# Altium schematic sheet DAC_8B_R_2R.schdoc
size 297 x 209 mm; Symbol: Drawing-Symbol_A4; @Project Name: Inverted_MAML_6x6; @Page Count: 1; @Update Date: 2026-06-15; @Create Date: 2026-06-15; @Schematic Name: Schematic1; @Page No: 1; @Page Name: P1; Company: EasyEDA.com; Version: V1.0; Page Size: A4; Drawn: Olle Welin; Device: Drawing-Symbol_A4; @Create Time: 20:58:38; @Update Time: 20:58:38; Border: 1; Width: 1170; Height: 825; Region Start: 1; X Region Count: 6; Y Region Count: 4; Blade Width: 10; Title Block Position: 3
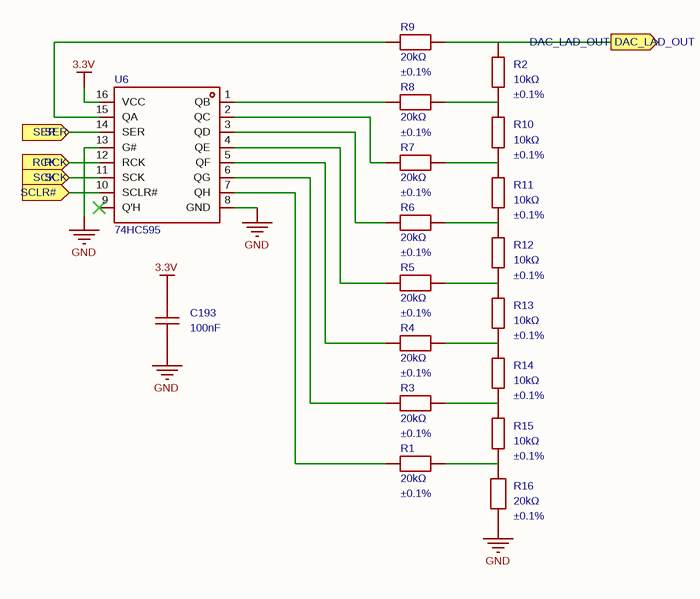
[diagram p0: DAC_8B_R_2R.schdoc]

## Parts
C193  100nF  [C0402]
R1  20kΩ  Tolerance: ±0.1%  [R0402]
R2  10kΩ  Tolerance: ±0.1%  [R0402]
R3  20kΩ  Tolerance: ±0.1%  [R0402]
R4  20kΩ  Tolerance: ±0.1%  [R0402]
R5  20kΩ  Tolerance: ±0.1%  [R0402]
R6  20kΩ  Tolerance: ±0.1%  [R0402]
R7  20kΩ  Tolerance: ±0.1%  [R0402]
R8  20kΩ  Tolerance: ±0.1%  [R0402]
R9  20kΩ  Tolerance: ±0.1%  [R0402]
R10  10kΩ  Tolerance: ±0.1%  [R0402]
R11  10kΩ  Tolerance: ±0.1%  [R0402]
R12  10kΩ  Tolerance: ±0.1%  [R0402]
R13  10kΩ  Tolerance: ±0.1%  [R0402]
R14  10kΩ  Tolerance: ±0.1%  [R0402]
R15  10kΩ  Tolerance: ±0.1%  [R0402]
R16  20kΩ  Tolerance: ±0.1%  [R0402]
U6  74HC595  [SOP-16_L9.9-W3.9-P1.27-LS6.0-BL]

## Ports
DAC_LAD_OUT (out), RCK (in), SCK (in), SCLR# (in), SER (in)

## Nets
3.3V: C193.2 U6.16(VCC)
GND: C193.1 R16.1 U6.8(GND) U6.13(G#)
DAC_LAD_OUT: R2.2 R9.2 ; port DAC_LAD_OUT
RCK: U6.12(RCK) ; port RCK
SCK: U6.11(SCK) ; port SCK
SCLR#: U6.10(SCLR#) ; port SCLR#
SER: U6.14(SER) ; port SER
NetR1_1: R1.1 U6.7(QH)
NetR1_2: R1.2 R15.1 R16.2
NetR2_1: R2.1 R8.2 R10.2
NetR3_1: R3.1 U6.6(QG)
NetR3_2: R3.2 R14.1 R15.2
NetR4_1: R4.1 U6.5(QF)
NetR4_2: R4.2 R13.1 R14.2
NetR5_1: R5.1 U6.4(QE)
NetR5_2: R5.2 R12.1 R13.2
NetR6_1: R6.1 U6.3(QD)
NetR6_2: R6.2 R11.1 R12.2
NetR7_1: R7.1 U6.2(QC)
NetR7_2: R7.2 R10.1 R11.2
NetR8_1: R8.1 U6.1(QB)
NetR9_1: R9.1 U6.15(QA)

Not connected (* = marked no-connect by the designer): U6 9(Q′H)*

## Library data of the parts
C193 = CL05B104KO5NNNC: Capacitance:100nF Tolerance:±10% Tolerance:±10% Voltage Rating:16V Temperature Coefficient:X7R; Manufacturer: SAMSUNG(三星); 3D Model: b7d13df3e9464d7a99d0651d1a5b4d570819f05c4eef4c71ace90d822a990e87; 3D Model Transform: 39.37,19.685,0,0,0,0,0,0,0; Tolerance: ±10%; Voltage Rating: 16V; Temperature Coefficient: X7R; AddInBom: yes; ModelName: C0402_L1.0-W0.5-H0.5
R1 R3-R9 R16 = ARG02BTC2002: Type:Thin Film Resistor Resistance:20kΩ Tolerance:±0.1% Tolerance:±0.1% Power(Watts):62.5mW Voltage-Supply(Max):50V Temperature Coefficient:±25ppm/℃ Temperature Coefficient:±25ppm/℃ Operating Temperature:-55℃~+155℃ Operating Temperature:-55℃~+155℃; Manufacturer: Viking(光颉); 3D Model: efdecb7dae4442949d28eecaf748420f; 3D Model Transform: 39.37,19.685,0,0,0,0,0,0,0; Power(Watts): 62.5mW; Voltage-Supply(Max): 50V; AddInBom: yes; ModelName: R0402_L1.0-W0.5-H0.4
R2 R10-R15 = RT0402BRD0710KL: Type:Thin Film Resistor Resistance:10kΩ Tolerance:±0.1% Tolerance:±0.1% Power(Watts):62.5mW Voltage-Supply(Max):50V Temperature Coefficient:±25ppm/℃ Temperature Coefficient:±25ppm/℃ Operating Temperature:-55℃~+155℃ Operating Temperature:-55℃~+155℃; Manufacturer: YAGEO(国巨); 3D Model: efdecb7dae4442949d28eecaf748420f; 3D Model Transform: 39.37,19.685,0,0,0,0,0,0,0; Power(Watts): 62.5mW; Voltage-Supply(Max): 50V; AddInBom: yes; ModelName: R0402_L1.0-W0.5-H0.4
U6 = 74HC595: Function:Serial-to-Serial or Parallel Voltage - Supply:2V~6V Voltage - Supply:2V~6V Clock Frequency:10MHz Number of Elements:1 Number of Bits per Element:8 Output Type:Tri-State Series:74HC Operating Temperature:-40℃~+85℃ Operating Temperature:-40℃~+85℃ P; Manufacturer: GR(国睿); 3D Model: 2f91ac34cbab4a3da9c51136f871f91e; 3D Model Transform: 389.763,236.22,0,0,0,0,0,0,0; Voltage - Supply: 2V~6V; Clock Frequency: 10MHz; Number of Elements: 1; Number of Bits per Element: 8; Propagation Delay: 100ns@5V,50pF; AddInBom: yes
